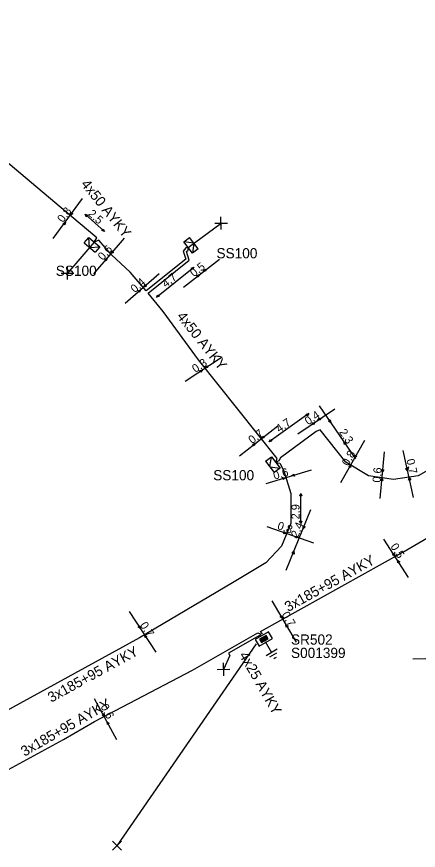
# Model space of a CAD drawing. Extents: x -762500 to -761285, y -1155006 to -1154135.
# Drawn here: x -761728.2 to -761689, y -1154672.9 to -1154591.6 of the extents above; entities that cross this region are included whole.
import ezdxf

# ---------------------------------------------------------------- set-up
doc = ezdxf.new("R2010")
doc.units = 0
for name, color, linetype in [('Vrstva 15', 7, 'Continuous'), ('Vrstva 28', 7, 'Continuous'), ('Vrstva 29', 7, 'Continuous'), ('Vrstva 30', 7, 'Continuous'), ('Vrstva 31', 7, 'Continuous'), ('Vrstva 33', 7, 'Continuous'), ('Vrstva 34', 7, 'Continuous'), ('Vrstva 40', 7, 'Continuous'), ('Vrstva 5', 7, 'Continuous'), ('Vrstva 59', 7, 'Continuous'), ('Vrstva 6', 7, 'Continuous')]:
    doc.layers.add(name, color=color, linetype=linetype)

msp = doc.modelspace()

# ---------------------------------------------------------------- linework, layer by layer
at = {"layer": 'Vrstva 15'}
for points in [[(-761703.976, -1154652.563), (-761703.351, -1154653.645)], [(-761702.809, -1154653.333), (-761703.892, -1154653.958)], [(-761702.863, -1154653.722), (-761703.545, -1154654.115)], [(-761703.038, -1154654.186), (-761703.149, -1154654.25)], [(-761702.923, -1154654.12), (-761703.038, -1154654.186)]]:
    msp.add_lwpolyline(points, dxfattribs=at)
at = {"layer": 'Vrstva 28'}
for points in [[(-761703.651, -1154651.631), (-761704.95, -1154652.381)], [(-761704.575, -1154653.03), (-761703.276, -1154652.28)], [(-761703.891, -1154651.981), (-761704.536, -1154652.353)], [(-761704.536, -1154652.353), (-761704.347, -1154652.681)], [(-761703.909, -1154652.046), (-761704.471, -1154652.371)], [(-761703.926, -1154652.11), (-761704.407, -1154652.388)], [(-761704.347, -1154652.681), (-761703.702, -1154652.309)], [(-761703.943, -1154652.175), (-761704.342, -1154652.405)], [(-761704.33, -1154652.616), (-761703.767, -1154652.291)], [(-761704.312, -1154652.552), (-761703.831, -1154652.274)], [(-761704.295, -1154652.487), (-761703.896, -1154652.257)], [(-761704.283, -1154652.425), (-761703.955, -1154652.236)], [(-761703.896, -1154652.257), (-761703.943, -1154652.175)], [(-761703.831, -1154652.274), (-761703.926, -1154652.11)], [(-761703.767, -1154652.291), (-761703.909, -1154652.046)], [(-761703.702, -1154652.309), (-761703.891, -1154651.981)], [(-761703.276, -1154652.28), (-761703.651, -1154651.631)], [(-761704.95, -1154652.381), (-761704.575, -1154653.03)], [(-761704.471, -1154652.371), (-761704.33, -1154652.616)], [(-761704.407, -1154652.388), (-761704.312, -1154652.552)], [(-761704.342, -1154652.405), (-761704.295, -1154652.487)]]:
    msp.add_lwpolyline(points, dxfattribs=at)
at = {"layer": 'Vrstva 31'}
for points in [[(-761721.649, -1154613.705), (-761721.199, -1154613.168), (-761720.126, -1154614.068), (-761720.576, -1154614.604)], [(-761721.112, -1154614.155), (-761721.199, -1154613.168)], [(-761710.518, -1154614.29), (-761711.077, -1154614.711), (-761711.919, -1154613.593), (-761711.36, -1154613.172)], [(-761710.518, -1154614.29), (-761711.36, -1154613.172)], [(-761721.649, -1154613.705), (-761720.576, -1154614.604)], [(-761721.112, -1154614.155), (-761720.126, -1154614.068)], [(-761710.939, -1154613.731), (-761711.919, -1154613.593)], [(-761710.939, -1154613.731), (-761711.077, -1154614.711)], [(-761703.932, -1154634.98), (-761703.373, -1154634.559), (-761702.531, -1154635.677), (-761703.09, -1154636.098)], [(-761703.932, -1154634.98), (-761703.09, -1154636.098)], [(-761703.511, -1154635.539), (-761703.373, -1154634.559)], [(-761703.511, -1154635.539), (-761702.531, -1154635.677)]]:
    msp.add_lwpolyline(points, dxfattribs=at)
at = {"layer": 'Vrstva 34'}
for points in [[(-761708.269, -1154612.395), (-761708.291, -1154611.145)], [(-761708.905, -1154611.781), (-761707.655, -1154611.759)], [(-761723.259, -1154617.275), (-761723.281, -1154616.025)], [(-761723.895, -1154616.661), (-761722.645, -1154616.639)], [(-761708.029, -1154655.915), (-761708.051, -1154654.665)], [(-761689.565, -1154654.261), (-761688.315, -1154654.239)], [(-761708.665, -1154655.301), (-761707.415, -1154655.279)], [(-761718.882, -1154672.058), (-761717.998, -1154672.942)], [(-761718.882, -1154672.942), (-761717.998, -1154672.058)]]:
    msp.add_lwpolyline(points, dxfattribs=at)
at = {"layer": 'Vrstva 40'}
for points in [[(-761724.66, -1154613.28), (-761721.79, -1154609.38)], [(-761721.55, -1154610.9), (-761719.66, -1154612.58)], [(-761720.71, -1154616.7), (-761717.7, -1154613.23)], [(-761711.96, -1154618.02), (-761708.44, -1154615.27)], [(-761714.58, -1154618.99), (-761710.95, -1154616.07)], [(-761717.64, -1154619.58), (-761714.31, -1154616.69)], [(-761711.78, -1154627.19), (-761708.18, -1154624.8)], [(-761698.7, -1154629.58), (-761695.18, -1154634.76)], [(-761699.73, -1154630.35), (-761703.6, -1154633.1)], [(-761700.78, -1154632.33), (-761697.18, -1154629.87)], [(-761706.5, -1154634.47), (-761702.75, -1154631.55)], [(-761696.61, -1154637.07), (-761694.25, -1154632.92)], [(-761692.75, -1154638.61), (-761692.35, -1154634.06)], [(-761689.5, -1154638.53), (-761690.53, -1154633.96)], [(-761699.48, -1154635.86), (-761703.93, -1154637.18)], [(-761700.51, -1154641.07), (-761700.5, -1154638.13)], [(-761701.93, -1154645.63), (-761699.52, -1154639.71)], [(-761699.23, -1154642.98), (-761703.79, -1154641.4)], [(-761689.99, -1154646.33), (-761692.4, -1154642.58)], [(-761703.32, -1154648.62), (-761700.94, -1154652.63)], [(-761717.25, -1154649.64), (-761714.64, -1154653.6)], [(-761718.45, -1154662.17), (-761720.62, -1154658.15)]]:
    msp.add_lwpolyline(points, dxfattribs=at)
for points in [[(-761722.972, -1154610.992), (-761722.91, -1154610.729), (-761722.741, -1154610.852)], [(-761723.468, -1154611.668), (-761723.53, -1154611.931), (-761723.699, -1154611.808)], [(-761721.552, -1154610.899), (-761721.295, -1154610.983), (-761721.433, -1154611.141)], [(-761719.658, -1154612.582), (-761719.915, -1154612.498), (-761719.777, -1154612.34)], [(-761719.012, -1154614.742), (-761718.932, -1154614.484), (-761718.772, -1154614.619)], [(-761719.398, -1154615.188), (-761719.478, -1154615.446), (-761719.638, -1154615.311)], [(-761710.948, -1154616.069), (-761711.076, -1154616.306), (-761711.207, -1154616.144)], [(-761710.022, -1154616.502), (-761709.895, -1154616.264), (-761709.763, -1154616.426)], [(-761710.388, -1154616.789), (-761710.515, -1154617.026), (-761710.647, -1154616.864)], [(-761715.822, -1154618.002), (-761715.707, -1154617.758), (-761715.567, -1154617.913)], [(-761716.128, -1154618.268), (-761716.243, -1154618.512), (-761716.383, -1154618.357)], [(-761714.582, -1154618.991), (-761714.455, -1154618.754), (-761714.323, -1154618.916)], [(-761710.108, -1154626.089), (-761710.256, -1154626.314), (-761710.373, -1154626.141)], [(-761709.843, -1154625.911), (-761709.695, -1154625.686), (-761709.578, -1154625.859)], [(-761699.728, -1154630.349), (-761699.868, -1154630.58), (-761699.991, -1154630.411)], [(-761699.127, -1154631.199), (-761699.271, -1154631.427), (-761699.391, -1154631.256)], [(-761698.832, -1154631.001), (-761698.688, -1154630.773), (-761698.568, -1154630.944)], [(-761697.578, -1154631.232), (-761697.807, -1154631.089), (-761697.635, -1154630.969)], [(-761704.332, -1154632.781), (-761704.201, -1154632.546), (-761704.072, -1154632.711)], [(-761704.918, -1154633.239), (-761705.049, -1154633.474), (-761705.178, -1154633.309)], [(-761703.602, -1154633.101), (-761703.462, -1154632.871), (-761703.339, -1154633.04)], [(-761696.311, -1154633.098), (-761696.083, -1154633.241), (-761696.254, -1154633.361)], [(-761695.241, -1154634.662), (-761695.212, -1154634.394), (-761695.03, -1154634.495)], [(-761695.619, -1154635.328), (-761695.648, -1154635.596), (-761695.831, -1154635.495)], [(-761692.52, -1154636.053), (-761692.603, -1154635.796), (-761692.395, -1154635.814)], [(-761690.09, -1154635.913), (-761690.247, -1154635.694), (-761690.044, -1154635.647)], [(-761702.008, -1154636.609), (-761702.215, -1154636.782), (-761702.276, -1154636.582)], [(-761701.402, -1154636.431), (-761701.195, -1154636.258), (-761701.134, -1154636.458)], [(-761692.57, -1154636.617), (-761692.487, -1154636.874), (-761692.695, -1154636.856)], [(-761689.94, -1154636.577), (-761689.783, -1154636.796), (-761689.986, -1154636.843)], [(-761700.5, -1154638.128), (-761700.395, -1154638.376), (-761700.604, -1154638.376)], [(-761700.51, -1154641.073), (-761700.615, -1154640.824), (-761700.406, -1154640.824)], [(-761700.271, -1154641.573), (-761700.275, -1154641.303), (-761700.081, -1154641.381)], [(-761701.898, -1154642.051), (-761702.167, -1154642.069), (-761702.099, -1154641.871)], [(-761701.123, -1154642.319), (-761700.854, -1154642.301), (-761700.922, -1154642.499)], [(-761701.169, -1154643.778), (-761701.165, -1154644.048), (-761701.359, -1154643.969)], [(-761691.319, -1154644.262), (-761691.542, -1154644.111), (-761691.367, -1154643.997)], [(-761691.071, -1154644.648), (-761690.848, -1154644.799), (-761691.023, -1154644.913)], [(-761702.299, -1154650.342), (-761702.516, -1154650.183), (-761702.337, -1154650.075)], [(-761716.149, -1154651.312), (-761716.374, -1154651.165), (-761716.201, -1154651.048)], [(-761701.961, -1154650.908), (-761701.744, -1154651.067), (-761701.923, -1154651.175)], [(-761715.741, -1154651.928), (-761715.516, -1154652.075), (-761715.689, -1154652.192)], [(-761719.669, -1154659.912), (-761719.881, -1154659.746), (-761719.698, -1154659.644)], [(-761719.401, -1154660.408), (-761719.189, -1154660.574), (-761719.372, -1154660.676)]]:
    msp.add_lwpolyline(points, close=True, dxfattribs=at)
at = {"layer": 'Vrstva 5'}
for points in [[(-761702.95, -1154635.12), (-761702.82, -1154634.74), (-761710.5, -1154625.1), (-761713.94, -1154620.4), (-761715.4, -1154618.6), (-761711.39, -1154615.39), (-761711.64, -1154614.55), (-761711.5, -1154614.39), (-761711.5, -1154614.15), (-761711.72, -1154614.19), (-761711.97, -1154614.49), (-761711.72, -1154615.27), (-761715.58, -1154618.36), (-761717.15, -1154616.55), (-761718.98, -1154614.85), (-761720.21, -1154613.42), (-761720.66, -1154613.62), (-761720.42, -1154613.21), (-761722.83, -1154611.14), (-761734.06, -1154601.73), (-761746.14, -1154591.63), (-761746.5, -1154591.84)], [(-761704.25, -1154651.83), (-761704.28, -1154651.79), (-761704.43, -1154651.59), (-761690.54, -1154643.85), (-761679.84, -1154637.62), (-761679.72, -1154637.91), (-761679.52, -1154638.01), (-761679.44, -1154637.79), (-761679.56, -1154637.46), (-761672.93, -1154633.76), (-761660.03, -1154626.27), (-761644.47, -1154617.44), (-761634.73, -1154611), (-761632.48, -1154609.17), (-761629.25, -1154606.05), (-761626.09, -1154601.36), (-761622.73, -1154594.39), (-761622.27, -1154593.22), (-761622.15, -1154593.27)], [(-761657.72, -1154600.17), (-761658.21, -1154600.5), (-761658.46, -1154600.16), (-761662.05, -1154602.71), (-761662.27, -1154602.94), (-761659.45, -1154606.64), (-761655.76, -1154611.62), (-761654.94, -1154614.27), (-761655.55, -1154616.01), (-761657.36, -1154618.35), (-761674.05, -1154627.87), (-761689.06, -1154636.42), (-761691.47, -1154636.76), (-761693.9, -1154636.43), (-761696.1, -1154635.07), (-761698.62, -1154631.94), (-761699.01, -1154632.1), (-761702.49, -1154634.66), (-761702.64, -1154634.96), (-761702.95, -1154635.12)], [(-761702.95, -1154635.12), (-761702.54, -1154635.17), (-761702.16, -1154635.93), (-761701.48, -1154638.13), (-761701.49, -1154641.07), (-761702.39, -1154643.28), (-761703.91, -1154644.9), (-761707.18, -1154646.86), (-761716.24, -1154652.23), (-761729.56, -1154659.53), (-761735.14, -1154662.55), (-761735.5, -1154662.4), (-761735.51, -1154662.76), (-761748.08, -1154669.62), (-761748.37, -1154669.45)], [(-761735.5, -1154668.57), (-761723.67, -1154662.14), (-761720.62, -1154660.39), (-761711.07, -1154655.38), (-761704.7, -1154651.74), (-761704.48, -1154651.84), (-761704.36, -1154651.9)], [(-761704.48, -1154651.96), (-761704.77, -1154652.13), (-761707.56, -1154653.72), (-761707.43, -1154653.94)]]:
    msp.add_lwpolyline(points, dxfattribs=at)
at = {"layer": 'Vrstva 59'}
for points in [[(-761711.5, -1154614.15), (-761708.28, -1154611.77)], [(-761720.66, -1154613.62), (-761723.27, -1154616.65)], [(-761704.85, -1154652.81), (-761718.44, -1154672.5)], [(-761707.43, -1154653.94), (-761708.04, -1154655.29)]]:
    msp.add_lwpolyline(points, dxfattribs=at)

# ---------------------------------------------------------------- texts
at = {"layer": 'Vrstva 29'}
msp.add_text('S001399', height=0.9943, dxfattribs=at).set_placement((-761701.46, -1154654.18))
at = {"layer": 'Vrstva 30'}
msp.add_text('SR502', height=0.9943, dxfattribs=at).set_placement((-761701.46, -1154652.88))
at = {"layer": 'Vrstva 33'}
for p in [(-761708.73, -1154615.2), (-761724.41, -1154616.91), (-761709.05, -1154636.85)]:
    msp.add_text('SS100', height=0.9943, dxfattribs=at).set_placement(p)
at = {"layer": 'Vrstva 40'}
for s, rotation, p in [('0,8', 53.67084, (-761723.7, -1154611.77)), ('2,5', 318.51612, (-761721.32, -1154610.95)), ('0,6', 49.08673, (-761719.8, -1154615.46)), ('0,5', 38.04351, (-761710.93, -1154617.06)), ('0,4', 41.05663, (-761716.7, -1154618.61)), ('4,7', 38.81339, (-761713.67, -1154618.1)), ('0,3', 33.69381, (-761710.79, -1154626.39)), ('0,4', 34.37981, (-761699.78, -1154631.5)), ('4,7', 35.37749, (-761702.6, -1154632.24)), ('0,7', 37.94481, (-761705.24, -1154633.34)), ('2,3', 304.18397, (-761696.8, -1154632.16)), ('0,8', 60.44061, (-761695.87, -1154635.52)), ('0,7', 282.61737, (-761690.21, -1154634.85)), ('0,6', 16.442, (-761703.06, -1154636.8)), ('0,6', 84.98715, (-761692.73, -1154637.1)), ('2,9', 89.80484, (-761700.63, -1154640.66)), ('0,8', 340.91229, (-761702.86, -1154641.59)), ('2,4', 67.84241, (-761700.78, -1154642.5)), ('0,5', 302.66479, (-761691.79, -1154643.3)), ('0,7', 300.81322, (-761702.4, -1154649.94)), ('0,7', 303.48087, (-761716.23, -1154650.98)), ('0,6', 298.3681, (-761720.07, -1154658.92))]:
    msp.add_text(s, height=0.7954, rotation=rotation, dxfattribs=at).set_placement(p)
at = {"layer": 'Vrstva 6'}
for s, height, rotation, p in [('4x50 AYKY', 0.9943, 308.72856, (-761722.01, -1154607.99)), ('4x50 AYKY', 0.9943, 308.55961, (-761712.66, -1154620.88)), ('3x185+95 AYKY', 0.99429, 29.11376, (-761701.74, -1154649.71)), ('3x185+95 AYKY', 0.99429, 28.72486, (-761724.85, -1154658.55)), ('4x25 AYKY', 0.9943, 299.71642, (-761706.56, -1154653.9)), ('3x185+95 AYKY', 0.99428, 29.84593, (-761727.46, -1154663.82))]:
    msp.add_text(s, height=height, rotation=rotation, dxfattribs=at).set_placement(p)

doc.saveas('drawing.dxf')
